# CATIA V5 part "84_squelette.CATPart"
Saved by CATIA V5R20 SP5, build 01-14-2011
Part number: 84_squelette
Publications: "Plan yz", "Plan.1", "Point.1"
Bounding box of the stored display mesh (mm): x 0 to 0, y 47.362 to 47.362, z -70.294 to -70.294
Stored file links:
  C:\Documents and Settings\anizard\Bureau\13\84_squelette.CATPart
  C:\Documents and Settings\anizard\Bureau\13\anizard.CATProduct
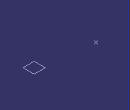
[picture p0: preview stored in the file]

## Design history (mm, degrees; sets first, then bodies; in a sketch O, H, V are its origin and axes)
Parameters
  epaisseur = 12 mm
Set1
  Point1: linked copy from another document
  Plane1: linked copy from another document
Body1 (main body)
  Plane2: type Offset, RefPlane Plane1, Offset 12 {= epaisseur}
  Point2: (0, 14, 0), relative to Point1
